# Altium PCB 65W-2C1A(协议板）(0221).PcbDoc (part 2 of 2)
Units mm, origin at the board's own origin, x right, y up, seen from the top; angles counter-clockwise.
Board outline 49.16 x 94.2 mm, 4 copper layers (Top Layer, Mid-Layer 1, Mid-Layer 2, Bottom Layer); 54 components, 359 nets, 243 pads, 110 vias.
Unrouted connection lines stored in the file: 1.
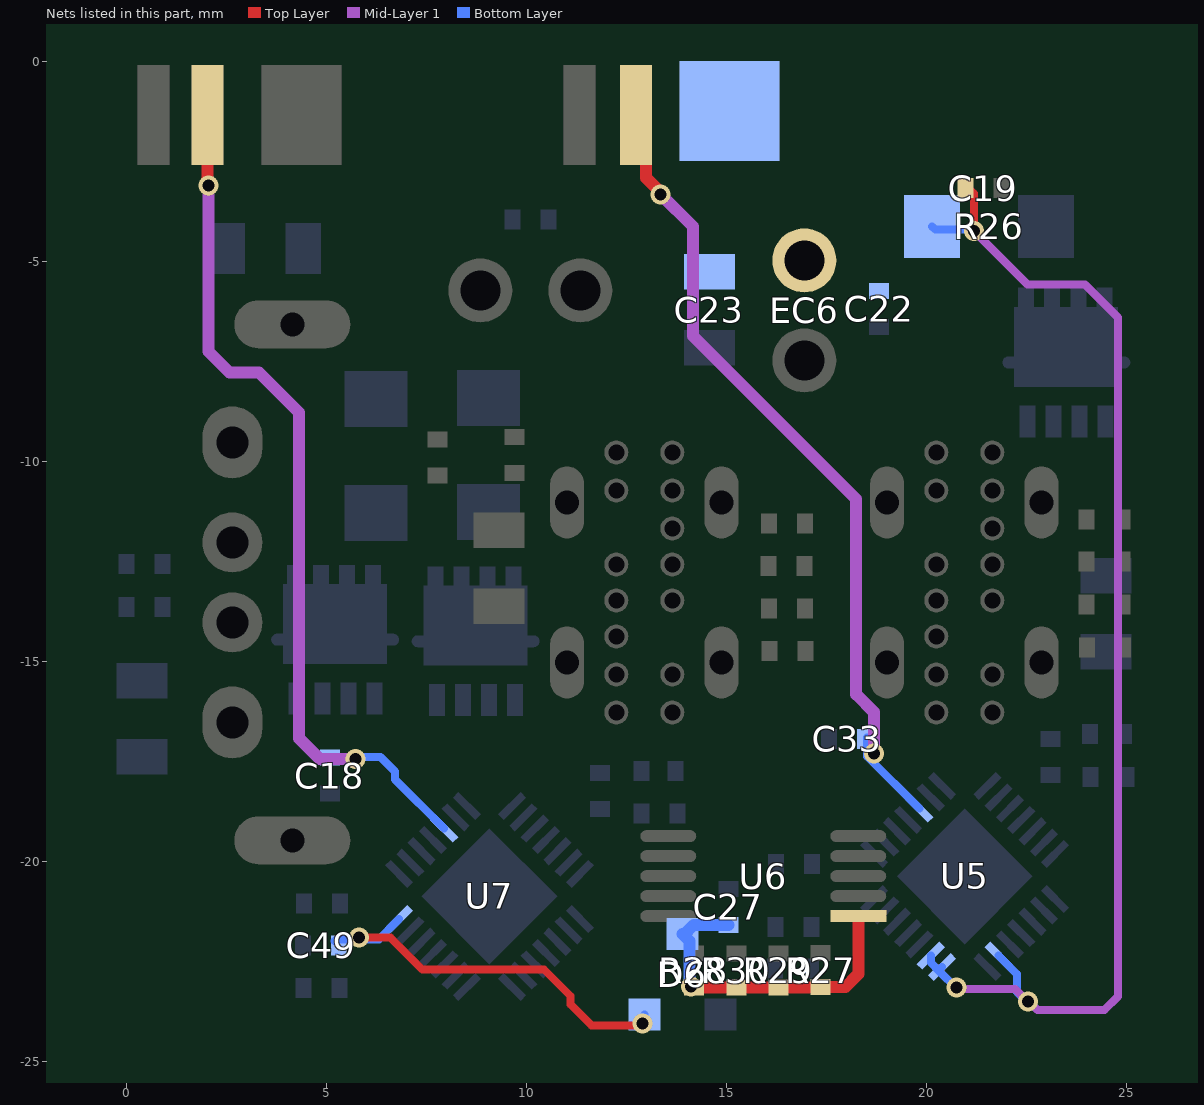
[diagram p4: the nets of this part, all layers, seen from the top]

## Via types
v1: diameter 0.5, hole 0.3, Top Layer to Bottom Layer, tented both sides, 110 vias

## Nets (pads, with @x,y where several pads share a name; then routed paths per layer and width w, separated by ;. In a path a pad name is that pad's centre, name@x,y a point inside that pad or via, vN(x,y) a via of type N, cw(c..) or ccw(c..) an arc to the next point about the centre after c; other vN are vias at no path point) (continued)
VDRV_C: C49.2 D6.2 U7.14 | length 10.2
  Top Layer w0.2: v1(5.81,-21.9) 6.593,-21.9 7.393,-22.7 10.438,-22.7 11.1,-23.362 11.1,-23.568 11.622,-24.09 12.86,-24.09 v1(12.9,-24.05)
  Bottom Layer w0.2: C49.2@5.2,-21.98 5.24,-21.94 6.303,-21.94 U7.14@6.807,-21.436 ; v1(12.9,-24.05) 12.94,-24.01 D6.2@12.94,-23.822
VFB: 
VIN: C18.2 C33.2 pad.0@2.02,-1.333 pad.0@12.738,-1.333 U5.19 U7.19 | length 42.8
  Top Layer w0.3: v1@2.02,-3.04 pad.0@2.02,-1.333 ; pad.0@12.738,-1.333 12.738,-2.183 12.988,-2.433 12.988,-2.908 13.346,-3.266 v1(13.346,-3.32)
  Mid-Layer 1 w0.3: v1(2.05,-3.1) 2.05,-7.25 2.568,-7.768 3.303,-7.768 4.31,-8.776 4.31,-16.909 4.316,-16.914 ; 4.31,-16.92 4.82,-17.43 5.715,-17.43 v1(5.719,-17.427) ; v1(13.346,-3.32) 13.354,-3.32 14.16,-4.126 14.16,-6.86 18.235,-10.935 18.235,-15.814 18.68,-16.259 v1(18.68,-17.3)
  Bottom Layer w0.2: C18.2@5.29,-17.42 5.712,-17.42 v1(5.719,-17.427) ; v1@5.719,-17.42 5.754,-17.385 6.055,-17.385 6.06,-17.38 6.348,-17.38 6.71,-17.742 6.71,-17.944 U7.19@7.939,-19.173 ; C33.2@18.51,-16.9 18.51,-17.364 U5.19@19.819,-18.673
VINC1: 
VINC2: 
VMCU: C27.1 D6.3 R27.1 R28.2 R29.1 R30.2 U6.1 | length 8.4
  Top Layer w0.3: v1(14.112,-23.114) 14.128,-23.13 14.14,-23.13 14.155,-23.145 15.225,-23.145 15.24,-23.13 15.255,-23.145 16.275,-23.145 16.29,-23.13 16.3,-23.14 17.34,-23.14 R27.1@17.35,-23.13 ; R27.1@17.35,-23.135 17.965,-23.135 18.27,-22.83 18.29,-22.81 U6.1@18.29,-21.36
  Bottom Layer w0.3: D6.3@13.89,-21.802 14.074,-21.986 14.074,-23.076 v1(14.112,-23.114) ; D6.3@13.94,-21.82 14.18,-21.58 C27.1@15.04,-21.58
VOUT: 
VOUT_A: C19.2 C22.2 C23.2 EC6.1 pad.0@15.07,-1.23 R26.1 U5.6 U5.8 U5.9 | length 30.8
  Top Layer w0.2: C19.2@21.04,-3.16 21.18,-3.3 v1(21.18,-4.23)
  Mid-Layer 1 w0.2: v1@20.75,-23.17 20.76,-23.18 22.21,-23.18 v1(22.53,-23.5) ; v1(21.18,-4.23) 22.52,-5.57 23.954,-5.57 24.78,-6.396 24.78,-23.37 24.44,-23.71 22.77,-23.71 v1@22.52,-23.46
  Bottom Layer w0.2: U5.9@20.101,-22.35 20.101,-22.521 U5.8@20.299,-22.719 ; R26.1@20.135,-4.12 20.215,-4.2 v1@21.16,-4.2 ; U5.8@20.384,-22.633 U5.8@20.299,-22.719 ; v1@20.77,-23.19 U5.8@20.299,-22.719 ; U5.6@21.799,-22.35 22.26,-22.811 22.26,-23.26 v1@22.53,-23.53
  other v1: 20.74,-23.15
VREG1: 
VREG2: 
VS-: 
pads on no net: U5.11 U5.23 U5.27 U5.28 U6.2 U6.4 U6.8 U6.9

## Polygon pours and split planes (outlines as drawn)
CSPA on Bottom Layer "Signal Layer 1-No Net" (solid, remove dead copper, pour order 110): 3.35,-0.1 3.35,-4.98 3.82,-5.45 4.03,-5.66 7.32,-5.66 7.56,-5.9 7.56,-6.12 7.5,-6.18 7.3,-6.38 6.83,-6.38 5.71,-7.5 5.71,-7.65 5.71,-9.12 5.73,-9.14 9.88,-9.14 9.93,-9.09 9.93,-3.17 9.44,-2.68 5.52,-2.68 5.41,-2.57 5.41,-0.08 5.3,0.03 3.41,0.03 3.35,-0.03
VBUSA on Bottom Layer "Signal Layer 1-No Net" (solid, remove dead copper, pour order 111): 4.66,-15.58 4.66,-16.69 4.864,-16.9 6.344,-16.9 6.51,-16.73 6.51,-15.72 6.51,-15.52 6.393,-15.4 4.777,-15.4 4.66,-15.52
CSNA on Bottom Layer "Signal Layer 1-No Net" (solid, remove dead copper, pour order 113): 5.53,-10.58 4.35,-10.58 3.64,-11.296 3.64,-14.928 3.85,-15.14 6.8,-15.14 6.88,-15.059 6.88,-12.093 7.02,-11.952 7.02,-10.61 6.99,-10.58
CSNC_C on Bottom Layer "Signal Layer 1-No Net" (solid, remove dead copper, pour order 114): 9.4,-10.55 8.11,-10.55 7.37,-11.29 7.37,-13.75 7.13,-13.99 7.13,-14.95 7.36,-15.18 10.06,-15.18 10.32,-14.92 10.32,-10.81 10.06,-10.55
VBUSC_C on Bottom Layer "Signal Layer 1-No Net" (solid, remove dead copper, pour order 115): 8.19,-15.6 8.19,-16.76 8.32,-16.89 8.5,-17.07 9.59,-17.07 10.21,-17.07 10.35,-16.93 10.35,-15.61 10.14,-15.4 8.33,-15.4 8.2,-15.53
VBUSC_C on Bottom Layer "Signal Layer 1-No Net" (solid, remove dead copper, pour order 116): 8.18,-15.55 8.18,-16.77 8.51,-17.1 10.47,-17.1 10.8,-17.43 14.35,-17.43 14.47,-17.31 14.47,-10.51 14.04,-10.08 11.69,-10.08 11.46,-10.31 11.46,-14.73 10.78,-15.41 8.33,-15.41
VBUSC_A on Bottom Layer "Signal Layer 1-No Net" (solid, remove dead copper, pour order 128): 22.96,-9.24 22.96,-8.6 23.06,-8.5 25.08,-8.5 25.37,-8.79 25.37,-13.65 25.15,-13.87 25.06,-13.96 23.07,-13.96 22.81,-13.96 22.44,-14.33 22.44,-15.79 22.31,-15.92 19.84,-15.92 19.37,-15.45 19.37,-10.27 19.54,-10.1 22.18,-10.1 22.61,-10.1 22.96,-9.75
VOUT_A on Bottom Layer "Signal Layer 1-No Net" (solid, remove dead copper, pour order 134): 13.78,-0.02 13.78,-5.73 13.98,-5.93 14.28,-6.23 16.8,-6.23 20.33,-6.23 20.83,-5.73 20.83,-3.14 20.51,-2.82 16.71,-2.82 16.36,-2.47 16.36,-0.1 16.27,-0.01
CSNC_A on Bottom Layer "NONET_L01_P-001" (solid, remove dead copper, pour order 162): 22.27,-5.9 21.91,-6.26 21.91,-7.94 22.16,-8.19 25.1,-8.19 25.24,-8.05 25.24,-3.48 24.59,-2.83 22.63,-2.83 22.27,-3.19
SGND on Bottom Layer "Top Layer-No Net" (solid, pour order 187): -0.93,-2.3 25.36,-2.3 25.86,-2.8 25.86,-23.77 25.02,-24.61 -0.2,-24.61 -0.26,-24.55 -0.37,-24.55 -1.04,-23.88 -1.04,-2.35
VBUSA on Bottom Layer "Top Layer-No Net" (solid, remove dead copper, pour order 188): 1.24,-16.85 1.72,-16.37 1.72,-15.96 2.13,-15.55 3.15,-15.55 3.61,-16.01 3.61,-17.12 2.3,-18.43 -0.37,-18.43 -0.65,-18.15 -0.65,-17.17 -0.33,-16.85
SGND on Top Layer "NONET_L01_P-001" (solid, remove dead copper, pour order 163): -1.035,-2.46 -1.035,-23.88 -0.435,-24.48 24.895,-24.48 25.545,-23.83 25.545,-2.43 25.485,-2.37 16.545,-2.37 16.415,-2.24 16.415,-0.11 16.285,0.02 13.785,0.02 13.745,-0.02 13.745,-2.39 13.565,-2.57 5.895,-2.57 5.585,-2.26 5.585,-0.13 5.455,0 3.365,0 3.225,-0.14 3.225,-2.28 3.055,-2.45
VBUSC_C on Top Layer "Signal Layer 1-No Net" (solid, remove dead copper, pour order 117): 8.3,-16.48 8.3,-12.77 8.5,-12.57 10.41,-12.57 10.98,-12 10.98,-10.55 11.29,-10.24 14.08,-10.24 14.34,-10.5 14.34,-15.72 14.34,-16.99 14.07,-17.26 9.02,-17.26 8.3,-16.54
VBUSA on Top Layer "Top Layer-No Net" (solid, pour order 186): -0.2,-15.02 5.58,-15.02 6.06,-15.5 6.06,-16.53 5.45,-17.14 4.73,-17.14 3.52,-18.35 -0.37,-18.35 -0.66,-18.06 -0.66,-15.42 -0.26,-15.02
no net on Top Overlay "Bottom Layer-No Net" (solid): 3.927,-22.074 3.966,-21.858 3.931,-21.858 3.893,-22.074
no net on Top Overlay "Bottom Layer-No Net" (solid): 3.521,-22.074 3.718,-22.074 3.74,-22.07 3.752,-22.067 3.764,-22.062 3.774,-22.056 3.784,-22.048 3.791,-22.039 3.798,-22.024 3.802,-22.007 3.801,-21.992 3.8,-21.986 3.795,-21.979 3.79,-21.974 3.781,-21.97 3.772,-21.967 3.765,-21.964 3.754,-21.963 3.579,-21.961 3.571,-21.96 3.565,-21.956 3.558,-21.951 3.554,-21.946 3.552,-21.943 3.55,-21.938 3.549,-21.933 3.548,-21.929 3.548,-21.924 3.548,-21.92 3.549,-21.916 3.55,-21.911 3.551,-21.907 3.553,-21.904 3.556,-21.899 3.558,-21.896 3.564,-21.89 3.567,-21.887 3.571,-21.885 3.581,-21.881 3.586,-21.88 3.597,-21.879 3.613,-21.879 3.635,-21.879 3.793,-21.878 3.809,-21.859 3.589,-21.858 3.566,-21.863 3.553,-21.869 3.54,-21.876 3.529,-21.888 3.52,-21.905 3.514,-21.923 3.513,-21.944 3.519,-21.953 3.522,-21.956 3.527,-21.961 3.537,-21.965 3.545,-21.967 3.553,-21.967 3.573,-21.968 3.74,-21.971 3.751,-21.974 3.758,-21.979 3.762,-21.982 3.765,-21.987 3.767,-21.992 3.769,-21.996 3.769,-22.002 3.769,-22.008 3.765,-22.024 3.763,-22.029 3.761,-22.033 3.757,-22.037 3.754,-22.04 3.747,-22.045 3.741,-22.047 3.735,-22.048 3.724,-22.051 3.707,-22.051 3.54,-22.053 3.521,-22.074
no net on Top Overlay "Bottom Layer-No Net" (solid): 2.92,-21.859 2.727,-22.073 2.716,-22.077 2.693,-22.078 2.684,-22.072 2.679,-22.062 2.573,-21.859 2.788,-21.859 2.771,-21.877 2.682,-21.88 2.672,-21.881 2.667,-21.883 2.662,-21.887 2.656,-21.893 2.652,-21.901 2.652,-21.905 2.651,-21.911 2.652,-21.915 2.652,-21.919 2.697,-22.01 2.703,-22.016 2.708,-22.019 2.713,-22.022 2.718,-22.024 2.722,-22.024 2.729,-22.024 2.734,-22.023 2.739,-22.021 2.743,-22.018 2.748,-22.014 2.755,-22.007 2.758,-22.002 2.884,-21.859
no net on Top Overlay "Bottom Layer-No Net" (solid): 1.998,-22.074 1.765,-22.074 1.761,-22.074 1.781,-22.054 1.862,-22.053 1.873,-22.051 1.878,-22.048 1.884,-22.042 1.889,-22.034 1.891,-22.023 1.92,-21.859 1.954,-21.859 1.929,-22.01 1.925,-22.017 1.925,-22.026 1.928,-22.035 1.934,-22.044 1.942,-22.05 1.95,-22.053 1.954,-22.053 2.017,-22.053
no net on Top Overlay "Bottom Layer-No Net" (solid): 1.488,-23.341 1.489,-23.326 1.655,-23.326 1.656,-23.405 1.523,-23.404 1.508,-23.356 1.489,-23.341
no net on Top Overlay "Bottom Layer-No Net" (solid): 1.181,-21.858 0.985,-22.076 0.978,-22.078 0.952,-22.078 0.945,-22.075 0.939,-22.066 0.831,-21.859 1.046,-21.859 1.03,-21.878 0.934,-21.879 0.925,-21.883 0.918,-21.889 0.914,-21.895 0.91,-21.904 0.91,-21.914 0.914,-21.926 0.958,-22.013 0.966,-22.021 0.975,-22.024 0.984,-22.025 0.993,-22.023 1.003,-22.018 1.011,-22.01 1.144,-21.859
no net on Top Overlay "Bottom Layer-No Net" (solid): 0.122,-22.065 0.353,-22.065 0.391,-21.848 0.174,-21.849 0.172,-21.848 0.155,-21.867 0.32,-21.87 0.332,-21.875 0.343,-21.886 0.346,-21.9 0.34,-21.935 0.33,-21.945 0.319,-21.95 0.308,-21.95 0.166,-21.95 0.154,-21.963 0.297,-21.963 0.309,-21.965 0.319,-21.972 0.326,-21.981 0.328,-21.99 0.325,-22.022 0.318,-22.034 0.311,-22.039 0.299,-22.042 0.295,-22.043 0.138,-22.043 0.119,-22.065
no net on Top Overlay "Bottom Layer-No Net" (solid): 2.679,-23.508 2.51,-23.508 2.498,-23.502 2.491,-23.494 2.486,-23.484 2.487,-23.223 2.494,-23.208 2.5,-23.196 2.504,-23.189 2.508,-23.184 2.514,-23.18 2.521,-23.177 2.534,-23.172 2.549,-23.168 2.559,-23.166 2.668,-23.166 2.673,-23.167 2.677,-23.168 2.683,-23.17 2.686,-23.173 2.69,-23.176 2.694,-23.181 2.696,-23.186 2.698,-23.192 2.698,-23.197 2.698,-23.481 2.695,-23.492 2.688,-23.499 2.681,-23.504 2.872,-23.504 2.871,-23.127 2.352,-23.127 2.33,-23.134 2.318,-23.145 2.312,-23.156 2.31,-23.165 2.31,-23.553 2.68,-23.552 2.679,-23.509
no net on Top Overlay "Bottom Layer-No Net" (solid): 2.872,-23.553 2.872,-23.501 2.686,-23.502 2.684,-23.502 2.682,-23.504 2.68,-23.506 2.677,-23.507 2.676,-23.508 2.666,-23.508 2.668,-23.552
no net on Top Overlay "Bottom Layer-No Net" (solid): 3.441,-21.86 3.347,-22.06 3.338,-22.071 3.333,-22.074 3.326,-22.078 3.308,-22.078 3.301,-22.071 3.299,-22.068 3.295,-22.056 3.288,-22.041 3.282,-22.022 3.25,-21.941 3.249,-21.933 3.248,-21.928 3.244,-21.921 3.241,-21.917 3.237,-21.913 3.23,-21.91 3.224,-21.908 3.214,-21.908 3.207,-21.909 3.2,-21.912 3.193,-21.917 3.189,-21.923 3.186,-21.93 3.186,-21.931 3.171,-21.952 3.083,-22.071 3.073,-22.078 3.05,-22.078 3.044,-22.072 3.041,-22.059 3.02,-21.859 3.055,-21.859 3.064,-21.958 3.064,-21.979 3.068,-21.989 3.074,-21.998 3.081,-22.003 3.091,-22.006 3.103,-22.005 3.111,-22.001 3.118,-21.994 3.209,-21.865 3.217,-21.858 3.226,-21.853 3.245,-21.853 3.254,-21.856 3.257,-21.863 3.295,-21.971 3.295,-21.979 3.298,-21.987 3.302,-21.994 3.306,-21.997 3.309,-21.999 3.315,-22.002 3.321,-22.004 3.327,-22.004 3.337,-22.003 3.341,-22.002 3.346,-21.999 3.351,-21.996 3.354,-21.991 3.358,-21.984 3.36,-21.978 3.36,-21.977 3.362,-21.971 3.412,-21.859
no net on Top Overlay "Bottom Layer-No Net" (solid): 2.387,-22.074 2.206,-22.074 2.186,-22.071 2.168,-22.067 2.157,-22.062 2.147,-22.056 2.142,-22.051 2.136,-22.044 2.133,-22.038 2.131,-22.032 2.13,-22.028 2.13,-22.011 2.135,-21.991 2.142,-21.979 2.146,-21.972 2.154,-21.964 2.161,-21.958 2.172,-21.95 2.184,-21.945 2.192,-21.942 2.197,-21.938 2.201,-21.932 2.204,-21.926 2.206,-21.92 2.206,-21.913 2.205,-21.907 2.202,-21.9 2.2,-21.896 2.192,-21.888 2.17,-21.859 2.22,-21.859 2.251,-21.906 2.254,-21.912 2.256,-21.916 2.259,-21.919 2.265,-21.923 2.275,-21.926 2.399,-21.925 2.411,-21.921 2.418,-21.915 2.423,-21.907 2.426,-21.901 2.432,-21.859 2.468,-21.859 2.453,-21.945 2.229,-21.947 2.214,-21.95 2.2,-21.956 2.19,-21.962 2.18,-21.972 2.173,-21.984 2.171,-21.993 2.171,-22.014 2.176,-22.027 2.183,-22.036 2.192,-22.043 2.211,-22.049 2.226,-22.051 2.248,-22.051 2.407,-22.05 2.386,-22.074
no net on Top Overlay "Bottom Layer-No Net" (solid): 1.665,-22.073 1.642,-21.862 1.638,-21.856 1.634,-21.854 1.631,-21.853 1.62,-21.853 1.614,-21.854 1.605,-21.86 1.597,-21.868 1.489,-22.014 1.482,-22.019 1.475,-22.022 1.467,-22.022 1.459,-22.021 1.453,-22.019 1.447,-22.014 1.443,-22.01 1.441,-22.006 1.385,-21.861 1.382,-21.857 1.377,-21.854 1.374,-21.853 1.363,-21.853 1.359,-21.854 1.348,-21.859 1.34,-21.869 1.243,-22.074 1.273,-22.074 1.326,-21.954 1.326,-21.95 1.328,-21.945 1.331,-21.939 1.336,-21.934 1.34,-21.931 1.346,-21.928 1.351,-21.927 1.356,-21.926 1.363,-21.927 1.369,-21.928 1.375,-21.931 1.378,-21.933 1.381,-21.935 1.384,-21.939 1.387,-21.944 1.389,-21.948 1.39,-21.952 1.39,-21.956 1.39,-21.96 1.43,-22.071 1.436,-22.078 1.461,-22.078 1.467,-22.074 1.472,-22.07 1.559,-21.949 1.563,-21.943 1.567,-21.938 1.571,-21.934 1.576,-21.931 1.583,-21.929 1.59,-21.928 1.596,-21.929 1.602,-21.932 1.607,-21.935 1.612,-21.939 1.615,-21.944 1.618,-21.951 1.631,-22.073
no net on Top Overlay "Bottom Layer-No Net" (solid): 0.724,-22.063 0.539,-22.063 0.526,-22.061 0.508,-22.057 0.501,-22.055 0.492,-22.051 0.484,-22.046 0.476,-22.039 0.468,-22.027 0.467,-22.024 0.467,-21.995 0.47,-21.985 0.475,-21.972 0.481,-21.964 0.49,-21.955 0.495,-21.949 0.504,-21.943 0.512,-21.938 0.524,-21.933 0.53,-21.929 0.534,-21.925 0.537,-21.921 0.539,-21.916 0.54,-21.911 0.541,-21.906 0.541,-21.901 0.54,-21.897 0.539,-21.893 0.537,-21.888 0.535,-21.884 0.525,-21.873 0.522,-21.869 0.516,-21.863 0.506,-21.849 0.556,-21.849 0.591,-21.901 0.598,-21.908 0.608,-21.913 0.616,-21.914 0.734,-21.916 0.746,-21.913 0.754,-21.907 0.761,-21.898 0.763,-21.885 0.77,-21.849 0.804,-21.849 0.79,-21.935 0.567,-21.936 0.549,-21.94 0.533,-21.947 0.519,-21.959 0.511,-21.97 0.506,-21.984 0.506,-22 0.508,-22.007 0.511,-22.016 0.515,-22.022 0.519,-22.026 0.526,-22.031 0.535,-22.035 0.543,-22.038 0.552,-22.039 0.564,-22.041 0.744,-22.041
no net on Top Overlay "Bottom Layer-No Net" (solid): 1.656,-23.406 0.893,-23.405 0.892,-23.251 0.894,-23.241 0.896,-23.228 0.903,-23.215 0.907,-23.209 0.915,-23.201 0.923,-23.195 0.938,-23.19 0.959,-23.187 1.657,-23.189 1.656,-23.339 1.489,-23.339 1.488,-23.339 1.487,-23.344 1.486,-23.349 1.483,-23.353 1.48,-23.357 1.476,-23.361 1.471,-23.364 1.463,-23.366 1.458,-23.366 1.108,-23.366 1.1,-23.365 1.094,-23.362 1.088,-23.357 1.085,-23.353 1.083,-23.35 1.081,-23.345 1.08,-23.341 1.08,-23.336 1.08,-23.283 1.082,-23.274 1.086,-23.263 1.092,-23.253 1.102,-23.244 1.11,-23.24 1.123,-23.236 1.132,-23.234 1.458,-23.234 1.463,-23.234 1.467,-23.235 1.472,-23.237 1.476,-23.24 1.48,-23.243 1.482,-23.246 1.485,-23.25 1.487,-23.255 1.488,-23.26 1.489,-23.264 1.488,-23.335 1.654,-23.334
no net on Top Overlay "Bottom Layer-No Net" (solid): 3.617,-23.552 3.421,-23.552 ccw(c3.397,-23.552) 3.397,-23.528 3.387,-23.528 2.962,-23.527 2.962,-23.483 3.229,-23.481 3.232,-23.481 3.237,-23.479 3.242,-23.477 3.246,-23.475 3.249,-23.472 3.252,-23.468 3.255,-23.464 3.257,-23.46 3.259,-23.455 3.282,-23.407 3.283,-23.405 3.284,-23.4 3.285,-23.395 3.284,-23.39 3.283,-23.385 3.281,-23.381 3.279,-23.377 3.276,-23.373 3.272,-23.37 3.268,-23.368 3.263,-23.366 3.259,-23.365 3.254,-23.364 2.962,-23.364 2.962,-23.318 2.983,-23.317 2.991,-23.316 2.998,-23.312 3.005,-23.305 3.01,-23.295 3.011,-23.285 3.009,-23.277 2.969,-23.126 3.145,-23.126 3.187,-23.286 3.187,-23.292 3.19,-23.301 3.196,-23.309 3.199,-23.312 3.204,-23.314 3.209,-23.316 3.218,-23.318 3.302,-23.318 3.309,-23.316 3.315,-23.314 3.321,-23.31 3.325,-23.306 3.328,-23.3 3.33,-23.296 3.331,-23.29 3.4,-23.126 3.658,-23.125 3.59,-23.276 3.589,-23.283 3.589,-23.289 3.59,-23.293 3.592,-23.298 3.595,-23.303 3.598,-23.306 3.6,-23.308 3.603,-23.31 3.605,-23.312 3.609,-23.313 3.614,-23.315 3.619,-23.315 3.671,-23.316 3.671,-23.361 3.568,-23.362 3.557,-23.367 3.55,-23.373 3.545,-23.379 3.543,-23.388 3.542,-23.392 3.54,-23.396 3.516,-23.447 3.516,-23.457 3.518,-23.466 3.524,-23.474 3.53,-23.479 3.536,-23.481 3.543,-23.483 3.655,-23.483 3.617,-23.552
no net on Top Overlay "Bottom Layer-No Net" (solid): 1.411,-22.945 1.401,-22.885 1.399,-22.871 1.4,-22.865 1.403,-22.86 1.407,-22.855 1.411,-22.851 1.417,-22.848 1.417,-22.807 1.373,-22.807 1.365,-22.805 1.36,-22.803 1.356,-22.801 1.352,-22.798 1.349,-22.794 1.347,-22.79 1.345,-22.786 1.344,-22.781 1.343,-22.776 1.343,-22.445 1.199,-22.445 1.199,-22.778 1.196,-22.788 1.193,-22.794 1.189,-22.799 1.185,-22.801 1.178,-22.805 1.172,-22.806 1.169,-22.807 1.125,-22.807 1.125,-22.849 1.128,-22.85 1.131,-22.851 1.135,-22.854 1.137,-22.856 1.14,-22.859 1.142,-22.861 1.144,-22.865 1.145,-22.867 1.146,-22.87 1.147,-22.872 1.147,-22.875 1.147,-22.876 1.147,-22.881 1.147,-22.885 1.135,-22.946 1.208,-22.946 1.222,-22.87 1.224,-22.865 1.227,-22.86 1.23,-22.856 1.235,-22.853 1.238,-22.851 1.242,-22.849 1.247,-22.848 1.251,-22.848 1.284,-22.848 1.292,-22.849 1.3,-22.852 1.304,-22.855 1.308,-22.858 1.311,-22.864 1.313,-22.87 1.315,-22.875 1.328,-22.945 1.412,-22.945
no net on Top Overlay "Bottom Layer-No Net" (solid): 1.654,-23.551 0.894,-23.551 0.894,-23.497 1.654,-23.497
no net on Top Overlay "Bottom Layer-No Net" (solid): 7.995,-22.122 8.285,-22.123 8.128,-22.858 7.835,-22.858 7.801,-23.015 8.095,-23.015 7.974,-23.626 8.181,-23.601 8.285,-23.497 8.622,-21.955 8.598,-21.839 8.514,-21.781 8.07,-21.774
no net on Top Overlay "Bottom Layer-No Net" (solid): 6.022,-23.063 5.936,-22.403 5.928,-22.381 5.91,-22.36 5.893,-22.349 5.872,-22.339 5.847,-22.335 5.796,-22.335 5.767,-22.34 5.735,-22.352 5.702,-22.375 5.663,-22.412 5.325,-22.812 5.319,-22.818 5.309,-22.823 5.294,-22.826 5.285,-22.822 5.279,-22.819 5.274,-22.814 5.271,-22.809 5.268,-22.804 5.267,-22.793 5.094,-22.401 5.073,-22.37 5.048,-22.349 5.017,-22.337 4.983,-22.335 4.947,-22.335 4.916,-22.342 4.884,-22.356 4.857,-22.372 4.835,-22.393 4.805,-22.44 4.78,-22.482 4.465,-23.064 4.699,-23.064 4.912,-22.65 4.922,-22.639 4.932,-22.636 4.942,-22.636 4.947,-22.636 4.956,-22.641 4.965,-22.65 4.969,-22.668 5.099,-22.991 5.123,-23.037 5.142,-23.057 5.165,-23.07 5.188,-23.076 5.278,-23.076 5.313,-23.066 5.342,-23.051 5.364,-23.032 5.684,-22.647 5.69,-22.643 5.698,-22.64 5.709,-22.639 5.721,-22.644 5.729,-22.652 5.735,-22.665 5.777,-23.063 6.023,-23.063
no net on Top Overlay "Bottom Layer-No Net" (solid): 1.489,-22.447 1.652,-22.444 1.653,-23.095 0.888,-23.097 0.887,-22.477 0.894,-22.462 0.903,-22.455 0.91,-22.45 0.922,-22.446 0.941,-22.443 1.053,-22.445 1.054,-23.011 1.054,-23.014 1.055,-23.019 1.057,-23.023 1.059,-23.027 1.063,-23.032 1.066,-23.034 1.07,-23.036 1.074,-23.038 1.079,-23.039 1.084,-23.04 1.456,-23.04 1.465,-23.038 1.473,-23.035 1.48,-23.028 1.485,-23.019 1.487,-23.011 1.486,-22.976 1.489,-22.446
no net on Top Overlay "Bottom Layer-No Net" (solid): 0.88,-23.481 0.88,-22.72 0.879,-22.717 0.731,-22.717 0.727,-22.716 0.723,-22.715 0.719,-22.714 0.715,-22.711 0.711,-22.708 0.708,-22.704 0.705,-22.7 0.703,-22.695 0.702,-22.691 0.702,-22.687 0.702,-22.51 0.702,-22.507 0.703,-22.501 0.706,-22.496 0.708,-22.492 0.711,-22.489 0.714,-22.486 0.719,-22.483 0.723,-22.481 0.728,-22.48 0.733,-22.48 0.899,-22.479 0.899,-22.435 0.44,-22.433 0.416,-22.437 0.394,-22.449 0.382,-22.464 0.378,-22.48 0.378,-22.541 0.457,-22.541 0.457,-22.515 0.46,-22.508 0.463,-22.501 0.468,-22.495 0.474,-22.489 0.479,-22.486 0.487,-22.482 0.493,-22.48 0.497,-22.48 0.527,-22.48 0.534,-22.481 0.54,-22.483 0.546,-22.487 0.551,-22.493 0.555,-22.499 0.557,-22.509 0.557,-22.51 0.557,-22.691 0.551,-22.705 0.541,-22.713 0.529,-22.717 0.379,-22.717 0.379,-23.481 0.457,-23.481 0.456,-22.804 0.458,-22.796 0.462,-22.789 0.468,-22.783 0.476,-22.778 0.484,-22.776 0.531,-22.776 0.539,-22.779 0.547,-22.784 0.553,-22.791 0.557,-22.802 0.557,-23.395 0.554,-23.406 0.551,-23.411 0.547,-23.416 0.54,-23.421 0.532,-23.423 0.527,-23.423 0.487,-23.423 0.479,-23.423 0.471,-23.419 0.467,-23.415 0.462,-23.41 0.458,-23.401 0.458,-23.399 0.457,-23.481 0.53,-23.481 0.543,-23.486 0.549,-23.491 0.554,-23.499 0.557,-23.508 0.557,-23.542 0.702,-23.542 0.702,-23.511 0.703,-23.504 0.705,-23.498 0.709,-23.492 0.718,-23.484 0.725,-23.482 0.733,-23.481 0.734,-23.424 0.728,-23.423 0.723,-23.422 0.719,-23.42 0.715,-23.418 0.711,-23.415 0.708,-23.411 0.705,-23.407 0.703,-23.402 0.702,-23.398 0.702,-23.393 0.702,-22.806 0.703,-22.797 0.708,-22.789 0.714,-22.783 0.72,-22.779 0.728,-22.777 0.732,-22.776 0.769,-22.776 0.779,-22.778 0.787,-22.783 0.792,-22.788 0.795,-22.794 0.798,-22.802 0.798,-22.806 0.798,-23.398 0.793,-23.41 0.785,-23.418 0.778,-23.422 0.77,-23.423 0.733,-23.424 0.732,-23.481 0.879,-23.481
no net on Top Overlay "Bottom Layer-No Net" (solid): 3.673,-23.011 2.311,-23.011 2.312,-22.735 3.67,-22.735 3.669,-22.789 2.599,-22.79 2.586,-22.799 2.578,-22.815 2.577,-22.92 2.58,-22.929 2.584,-22.936 2.589,-22.94 2.594,-22.944 2.602,-22.947 2.607,-22.948 3.377,-22.948 3.386,-22.946 3.389,-22.944 3.395,-22.94 3.398,-22.937 3.4,-22.934 3.403,-22.928 3.405,-22.921 3.405,-22.818 3.403,-22.81 3.4,-22.804 3.395,-22.799 3.392,-22.796 3.387,-22.793 3.382,-22.792 3.375,-22.79 3.375,-22.789 3.671,-22.79
no net on Top Overlay "Bottom Layer-No Net" (solid): 2.607,-22.734 2.595,-22.73 2.587,-22.725 2.582,-22.718 2.578,-22.707 2.578,-22.704 2.578,-22.54 2.579,-22.535 2.582,-22.527 2.587,-22.518 2.591,-22.511 2.597,-22.506 2.606,-22.5 2.613,-22.496 2.62,-22.494 2.628,-22.491 2.635,-22.49 2.645,-22.489 2.656,-22.489 2.665,-22.488 3.377,-22.488 3.386,-22.49 3.392,-22.492 3.397,-22.496 3.402,-22.502 3.405,-22.507 3.407,-22.514 3.407,-22.518 3.407,-22.707 3.404,-22.718 3.4,-22.725 3.394,-22.73 3.387,-22.733 3.383,-22.734 3.382,-22.735 3.382,-22.736 3.67,-22.736 3.671,-22.445 2.37,-22.442 2.35,-22.446 2.333,-22.454 2.319,-22.468 2.312,-22.486 2.312,-22.738 2.606,-22.737
no net on Top Overlay "Bottom Layer-No Net" (solid): 4.378,-23.628 8.101,-23.628 8.101,-23.309 7.739,-23.309 4.378,-23.309
no net on Top Overlay "Bottom Layer-No Net" (solid): 6.186,-23.068 6.932,-23.068 7.013,-23.061 7.117,-23.038 7.181,-23.012 7.239,-22.97 7.279,-22.921 7.3,-22.877 7.312,-22.83 7.313,-22.779 7.306,-22.752 7.294,-22.73 7.274,-22.707 7.243,-22.685 7.211,-22.67 7.182,-22.661 7.134,-22.651 7.084,-22.646 6.564,-22.645 6.544,-22.644 6.52,-22.64 6.501,-22.633 6.494,-22.628 6.487,-22.621 6.482,-22.615 6.478,-22.606 6.477,-22.6 6.477,-22.575 6.48,-22.563 6.481,-22.558 6.483,-22.554 6.486,-22.55 6.49,-22.543 6.496,-22.536 6.499,-22.533 6.503,-22.53 6.508,-22.526 6.515,-22.523 6.524,-22.519 6.536,-22.516 6.545,-22.514 6.554,-22.513 6.559,-22.513 7.241,-22.51 7.419,-22.348 6.592,-22.348 6.536,-22.352 6.475,-22.363 6.428,-22.376 6.377,-22.398 6.344,-22.418 6.319,-22.438 6.297,-22.459 6.282,-22.478 6.265,-22.504 6.245,-22.551 6.236,-22.591 6.233,-22.607 6.233,-22.634 6.237,-22.656 6.244,-22.676 6.253,-22.692 6.269,-22.708 6.279,-22.717 6.293,-22.726 6.305,-22.733 6.332,-22.744 6.365,-22.754 6.395,-22.76 6.422,-22.764 6.457,-22.766 6.987,-22.768 7.027,-22.773 7.056,-22.782 7.073,-22.806 7.074,-22.836 7.067,-22.86 7.054,-22.876 7.03,-22.891 7.002,-22.897 6.365,-22.898 6.182,-23.067
no net on Top Overlay "Bottom Layer-No Net" (solid): 7.739,-23.309 8.07,-21.774 4.378,-21.777 4.378,-22.122 7.603,-22.123 7.351,-23.309 7.739,-23.309
VBUSC_A on Mid-Layer 1 "Signal Layer 1-No Net" (solid, remove dead copper, pour order 130): 22.5,-16.94 19.48,-16.94 18.84,-16.373 18.84,-8.519 19.38,-8.04 24.06,-8.04 24.56,-8.483 24.56,-16.382 23.94,-16.931
SGND on Mid-Layer 1 "NONET_L01_P-001" (solid, remove dead copper, pour order 166): -1.105,-2.685 -1.105,-23.725 -0.415,-24.415 25.215,-24.415 25.585,-24.045 25.585,-2.795 25.055,-2.265 -1.045,-2.265 -1.095,-2.315
SGND on Mid-Layer 2 "NONET_L01_P-001" (solid, remove dead copper, pour order 165): -0.945,-2.38 -0.945,-23.77 -0.235,-24.48 25.135,-24.48 25.665,-23.95 25.665,-2.65 25.257,-2.242 -0.821,-2.242

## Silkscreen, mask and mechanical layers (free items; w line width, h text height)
Mechanical 1:
  lines w0.1: -1.008,-23.515 -1.008,-2.465 -0.258,-2.465 ; -1.008,-23.465 ccw(c-0.008,-23.465) -0.008,-24.465 ; -0.273,-2.491 ccw(c-0.091,-2.401) -0.008,-2.215 -0.008,0.035 5.64,0.035 5.64,-2.2 ; -0.008,-24.465 24.592,-24.465 ; 5.64,-2.189 ccw(c5.731,-2.371) 5.91,-2.466 ; 5.89,-2.465 10.442,-2.465 ccw(c10.623,-2.375) 10.706,-2.189 ; 10.642,-2.165 10.642,0.035 16.59,0.035 16.59,-2.16 ; 16.59,-2.18 ccw(c16.681,-2.362) 16.854,-2.467 ; 16.87,-2.465 25.542,-2.465 25.542,-23.465 cw(c24.542,-23.465) 24.542,-24.465
Mechanical 2:
  lines w0.1: 18.19,-111.55 18.19,-74.45
  text "板厚1.0mm  2OZ   4层板" at -8.11,0.72 h0.8
Drill Drawing:
  text ".legend" at 2.45,1.06 h0.8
